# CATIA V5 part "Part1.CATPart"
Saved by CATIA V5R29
Part number: Part1
Bounding box of the stored display mesh (mm): x -4.95 to 4.95, y -100 to 31, z -4.941 to 4.941
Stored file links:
  C:\Users\Asus\Desktop\Part1.CATPart
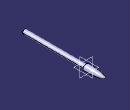
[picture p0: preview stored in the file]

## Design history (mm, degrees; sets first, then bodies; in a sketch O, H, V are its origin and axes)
Body1 (main body)
  Sketch1 on xy-plane, origin (0, 0, 0), H (1, 0, 0), V (0, 1, 0)
    ellipse A1 centre (0, 0) semi-axes 31, 4.95 rotation 90 from (0, 31) to (-4.95, 0)
    point P1 (0, 31)
    point P2 (4.95, 0)
    line L1 (0, 31) -> (0, 0)
    line L2 (0, 0) -> (-4.95, 0)
    distance P1 H = 31
    distance P2 V = 4.95
    coincidence: P1 V, P2 H
    vertical: L1 V
    horizontal: L2 H
  Shaft1: profile Sketch1, axis Sketch1.L1, angle 360
  Sketch2 on face of Shaft1 from Sketch1.L2, origin (0, 0, 0), H (1, 0, 0), V (0, 0, 1)
    circle A1 centre (0, 0) radius 3.5
    radius A1 = 3.5
  Pad1: profile Sketch2, direction (0, -1, 0), length 100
